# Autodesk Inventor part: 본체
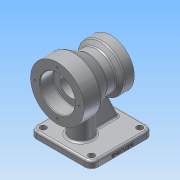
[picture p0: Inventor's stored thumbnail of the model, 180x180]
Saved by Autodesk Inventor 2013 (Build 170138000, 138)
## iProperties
Created: 2019-01
Part Number: 본체
Material: 알루미늄 6061
Document SubType Name: Modeling
Designer: Administrator
Density: 2.71 g/cm^3
Mass: 902.143 g
Surface Area: 600.963 cm^2
Volume: 332.894 cm^3
Author: Administrator
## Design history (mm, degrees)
sketch "스케치2"
  geometry: L1 (-35, 0)-(-35, 40); L2 (-35, 40)-(-10, 40); L3 (-10, 40)-(10.785, 28); L4 (10.785, 28)-(24.126, 28); L5 (24.126, 28)-(30, 35); L6 (30, 35)-(45, 35); L7 (45, 35)-(45, 0); L8 (45, 0)-(-35, 0); 1 further point
  constraints: 16 end point, 2 parallel, 2 perpendicular, 2 vertical, 1 point on line
  dimensions: "d1" = 80 diameter of L2 L8; "d3" = 70 diameter of L6 L8; "d5" = 50 deg angle of L4 L5; "d6" = 30 deg angle of L4 L3; "d7" = 15 distance of L5.end L6.end; "d8" = 25 distance of L1.end L2.end; "d9" = 80 distance of L7.end L1.start; "d10" = 56 diameter of L4 L8; "d11" = 35 distance of point (0, 0) L1.start
revolve "회전1" sketch "스케치2" stored, may be unused: angle "d12" = 90 deg
node "작업 평면1"
sketch "스케치3"
  geometry: L1 (30, 46)-(-62, 46); L2 (-62, 46)-(-62, -46); L3 (-62, -46)-(30, -46); L4 (30, -46)-(30, 46); 2 further points
  constraints: 8 end point, 2 parallel, 1 horizontal, 1 horizontal alignment, 1 midpoint, 1 perpendicular
  dimensions: "d14" = 92 distance of L2.end L3.end; "d16" = 92 distance of L1.end L2.end (= d14); "d17" = 30 distance of point (30, 0) point (0, 0)
extrude "돌출1" join sketch "스케치3" distance "d18" = 10; taper "d19" = 0 deg
sketch "스케치4"
  geometry: C1 r 16 at (0, 0); 1 further point
  constraints: 1 centre point, 1 coincident
  dimensions: "d20" = 32 diameter of C1
extrude "돌출2" join sketch "스케치4" stored distance "d21" = 10; taper "d22" = 0 deg
fillet "모깎기1" dims "d24" = 10
sketch "스케치5"
  geometry: L1 (52, -70)-(-20, -70) reference; L2 (52, -70)-(62, -70) reference; L3 (0, 0)-(45, 0); L4 (45, -35)-(45, 35) reference; L5 (52, -70)-(19.358, 0)
  constraints: 4 end point, 2 point on line, 1 midpoint
  dimensions: "d25" = 10 distance of L2.end L5.start; "d27" = 65 deg angle of L1 L5
feature "리브1" sketch "스케치5" dims "d28" = 1, "d29" = 10, "d30" = 0, "d31" = 0, "d32" = 1, "d33" = 1
sketch "스케치6"
  geometry: L1 (-35, -40)-(-35, 40) reference; L2 (45, -35)-(45, 35) reference; L3 (-35, 0)-(45, 0); L4 (45, 0)-(45, 20); L5 (45, 20)-(28, 20); L6 (30, -34.641)-(30, 35) reference; L7 (28, 20)-(28, 16); L8 (28, 16)-(-15, 16); L9 (-15, 16)-(-15, 26); L10 (-15, 26)-(-35, 26); L11 (-35, 26)-(-35, 0); 1 further point
  constraints: 16 end point, 3 perpendicular, 2 midpoint, 2 parallel, 2 point on line, 1 collinear
  dimensions: "d34" = 20 distance of L9.end L10.end; "d36" = 17 distance of L4.end L5.end; "d37" = 52 diameter of L10 L3; "d38" = 32 diameter of L8 L3; "d39" = 40 diameter of L5 L3
revolve "회전2" sketch "스케치6" stored, may be unused: angle "d40" = 90 deg
fillet "모깎기2" dims "d41" = 1
fillet "모깎기3" dims "d42" = 0.6
chamfer "모따기1" distance "d43" = 1; stored, may be unused: second distance "d44" = 2, angle "d45" = 45 deg
sketch "스케치7"
  geometry: C1 r 4.5 at (52, -36); A1 r 10 centre (52, -36) between (52, -46) and (62, -36) reference
  constraints: 1 centre point, 1 coincident
  dimensions: "d46" = 9 diameter of C1
extrude "돌출3" cut sketch "스케치7" stored distance "d47" = 10; taper "d48" = 0 deg
node "작업 평면2"
sketch "스케치8" dims "d49" = 55
  geometry: C1 r 35 at (0, 0) reference; C2 r 21 at (0, 0) reference; 2 further points
  constraints: 2 vertical alignment, 1 coincident, 2 other
hole "구멍1" sketch "스케치8" at (0, 27.5) diameter "d50" = 3.242; stored, may be unused: countersink angle "d54" = 90 deg, drill point angle "d56" = 118 deg; dims "d51" = 9, "d52" = 4, "d53" = 2, "d55" = 11
sketch "스케치9" dims "d60" = 66
  geometry: C1 r 40 at (0, 0) reference; C2 r 27 at (0, 0) reference; 2 further points
  constraints: 2 vertical alignment, 1 coincident, 2 other
hole "구멍2" sketch "스케치9" at (0, 33) diameter "d61" = 3.242; stored, may be unused: countersink angle "d65" = 90 deg, drill point angle "d67" = 118 deg; dims "d62" = 9, "d63" = 4, "d64" = 2, "d66" = 11
fillet "모깎기4" dims "d71" = 3
fillet "모깎기5" dims "d72" = 3
fillet "모깎기6" dims "d73" = 3
fillet "모깎기7" dims "d74" = 3
fillet "모깎기8" dims "d75" = 3
node "작업 평면3"
sketch "스케치10"
  geometry: L1 (0, 0)-(72, 0) reference; L2 (-10, 7)-(-10, 0) reference; 2 further points
  constraints: 1 other
  dimensions: "d77" = 4 distance from line of point (36, 4) L1; "d78" = 46 distance from line of L2 point (36, 4)
feature "엠보싱1" sketch "스케치10" dims "d79" = 0.5, "d80" = 0
node "솔리드1"
mirror "대칭1"
mirror "대칭2"
pattern_circular "원형 패턴1" dims angle "d58" = 360 deg
pattern_circular "원형 패턴2" dims angle "d69" = 360 deg
other parameters: "d76" = 16
